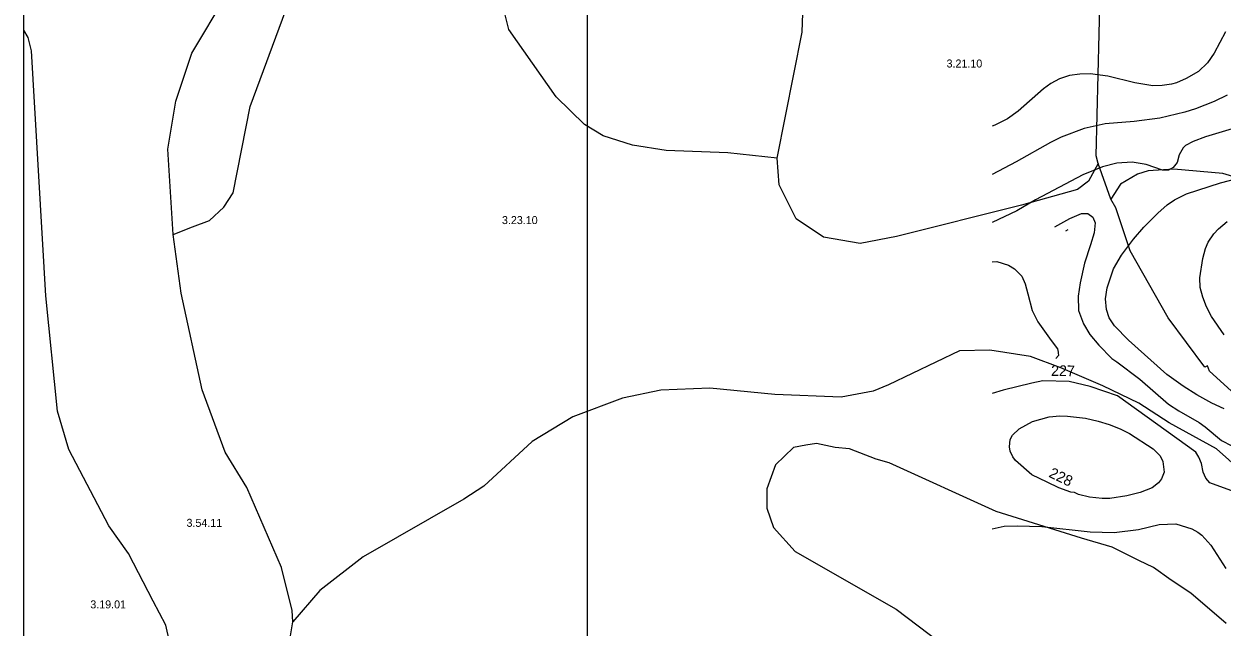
# Model space of a CAD drawing. Extents: x -662500 to -653478, y -1056827 to -1049993.
# Drawn here: x -662500 to -661377, y -1052752 to -1052187 of the extents above; entities that cross this region are included whole.
import ezdxf

# ---------------------------------------------------------------- set-up
doc = ezdxf.new("R2010")
doc.units = 0
for name, color, linetype in [('Vrstva 24', 7, 'Continuous'), ('Vrstva 7', 7, 'Continuous'), ('Vrstva 9', 7, 'Continuous')]:
    doc.layers.add(name, color=color, linetype=linetype)

msp = doc.modelspace()

# ---------------------------------------------------------------- linework, layer by layer
at = {"layer": 'Vrstva 24'}
for points in [[(-662500, -1052192.7), (-662500, -1052000), (-662500, -1051936.2)], [(-661794, -1052312.5), (-661840, -1052307.5), (-661898, -1052305.5), (-661929.5, -1052300.5), (-661957, -1052291.5), (-661974.5, -1052281), (-662001, -1052255), (-662045.5, -1052192), (-662051, -1052169.5), (-662044.5, -1052124.5), (-662027, -1052066), (-662005.5, -1052025.5), (-661977.2, -1052000), (-661965.5, -1051989.5), (-661936, -1051957)], [(-662360, -1052384), (-662342, -1052377), (-662326, -1052371), (-662312.5, -1052358.5), (-662304, -1052345), (-662288, -1052264), (-662254.5, -1052174), (-662230, -1052137.5), (-662217.5, -1052127.5), (-662164.5, -1052108), (-662148, -1052102), (-662118.5, -1052082), (-662096, -1052062.5), (-662083.5, -1052044.5), (-662081, -1052022), (-662089.6, -1052000), (-662090, -1051999), (-662093, -1051987), (-662096, -1051971)], [(-662360, -1052384), (-662365, -1052304), (-662357.5, -1052259), (-662342.5, -1052214), (-662310.5, -1052160), (-662296, -1052142), (-662284.5, -1052113), (-662279.5, -1052094.5), (-662275.5, -1052058.5), (-662267, -1052024)], [(-661794, -1052312.5), (-661770.5, -1052194.5), (-661769, -1052149.5), (-661771, -1052123), (-661774.5, -1052111), (-661778, -1052097), (-661789, -1052077.5), (-661800, -1052057), (-661815.5, -1052036)], [(-661493, -1052317.5), (-661495, -1052310.5), (-661491, -1052157.5), (-661494.5, -1052099), (-661494, -1052085), (-661500.5, -1052073), (-661505, -1052066), (-661512.5, -1052062), (-661538.5, -1052064.5), (-661566.5, -1052076), (-661606.5, -1052099.5), (-661625.5, -1052108), (-661655, -1052110), (-661691, -1052100), (-661737, -1052081), (-661750, -1052071.5)], [(-662500, -1053023.2), (-662500, -1052192.7)], [(-662500, -1053023.2), (-662494, -1053019.5), (-662486, -1053013), (-662479, -1053003.5), (-662475.3, -1053000), (-662456, -1052963.5), (-662427.5, -1052931), (-662414, -1052914), (-662397, -1052886.5), (-662363.5, -1052819.5), (-662359, -1052792.5), (-662358, -1052778), (-662363.5, -1052765.5), (-662367, -1052750), (-662379, -1052727.5), (-662402, -1052683), (-662420.5, -1052657), (-662458, -1052585.5), (-662468.5, -1052549.5), (-662479.5, -1052441.5), (-662493, -1052212), (-662496, -1052199.5), (-662500, -1052192.7)], [(-661493, -1052317.5), (-661502, -1052334), (-661512.5, -1052342), (-661565, -1052356.5), (-661682, -1052386), (-661716, -1052392.5), (-661750.5, -1052386.5), (-661776, -1052369.5), (-661792, -1052337.5), (-661794, -1052312.5)], [(-661481, -1052351), (-661493, -1052317.5)], [(-661227, -1052423), (-661235.5, -1052409), (-661260, -1052382), (-661282, -1052364), (-661292, -1052360), (-661300, -1052354), (-661317, -1052346), (-661346, -1052336), (-661376, -1052327), (-661422, -1052323), (-661446, -1052324.5), (-661456, -1052327.5), (-661472, -1052337), (-661481, -1052351)], [(-661304, -1052572.5), (-661358, -1052540), (-661388.5, -1052512), (-661390.5, -1052507), (-661393, -1052508.5), (-661427.5, -1052462), (-661463, -1052399.5), (-661476.5, -1052359), (-661481, -1052351)], [(-662248, -1052747), (-662248.5, -1052736.5), (-662258.5, -1052696), (-662291, -1052621), (-662311.5, -1052588), (-662333, -1052529.5), (-662352.5, -1052439), (-662360, -1052384)], [(-661359, -1052605.5), (-661382, -1052585), (-661426.5, -1052560.5), (-661455, -1052542), (-661488.5, -1052526), (-661528, -1052509), (-661556.5, -1052498.5), (-661594.5, -1052492.5), (-661623, -1052493), (-661689.5, -1052525), (-661704, -1052531), (-661734, -1052536.5), (-661796, -1052534), (-661857, -1052528), (-661903, -1052530), (-661939, -1052537.5), (-661985.5, -1052555), (-662023.5, -1052578), (-662069, -1052620), (-662087.5, -1052632), (-662182, -1052686), (-662222.5, -1052717.5), (-662248, -1052747)], [(-661373, -1052748.5), (-661406, -1052720), (-661424.5, -1052708), (-661441, -1052696), (-661455, -1052689.5), (-661480, -1052677), (-661508.5, -1052668.5), (-661588.5, -1052643.5), (-661689, -1052598), (-661701, -1052594.5), (-661726, -1052585), (-661739.5, -1052583.5), (-661757, -1052580), (-661767, -1052581.5), (-661778.5, -1052583.5), (-661795.5, -1052600), (-661803.5, -1052622.5), (-661803.5, -1052640.5), (-661797.5, -1052658.5), (-661777, -1052681), (-661682.5, -1052735), (-661569, -1052821)], [(-662346, -1053118), (-662332, -1053050.5), (-662319.3, -1053000), (-662298, -1052925), (-662255, -1052790), (-662248, -1052747)]]:
    msp.add_lwpolyline(points, dxfattribs=at)
at = {"layer": 'Vrstva 7'}
for p, q in [((-661373.6, -1052194.2), (-661384.2, -1052214.1)), ((-661390.5, -1052223.2), (-661399, -1052231.2)), ((-661384.2, -1052214.1), (-661390.5, -1052223.2)), ((-661510.2, -1052233.8), (-661519.9, -1052235.1)), ((-661500.6, -1052233.5), (-661510.2, -1052233.8)), ((-661483.9, -1052235.8), (-661500.6, -1052233.5)), ((-661399, -1052231.2), (-661410.4, -1052238)), ((-661537.4, -1052242.7), (-661544.2, -1052247.7)), ((-661529.1, -1052238.2), (-661537.4, -1052242.7)), ((-661519.9, -1052235.1), (-661529.1, -1052238.2)), ((-661458.6, -1052242), (-661483.9, -1052235.8)), ((-661441.6, -1052244.7), (-661458.6, -1052242)), ((-661433.1, -1052244.6), (-661441.6, -1052244.7)), ((-661424.1, -1052243.3), (-661433.1, -1052244.6)), ((-661419.5, -1052242), (-661424.1, -1052243.3)), ((-661410.4, -1052238), (-661419.5, -1052242)), ((-661544.2, -1052247.7), (-661567.9, -1052268.6)), ((-661372, -1052253.6), (-661384.1, -1052259.3)), ((-661401.7, -1052266.2), (-661411.6, -1052269.4)), ((-661384.1, -1052259.3), (-661401.7, -1052266.2)), ((-661578, -1052275.6), (-661589.9, -1052281.7)), ((-661567.9, -1052268.6), (-661578, -1052275.6)), ((-661459.2, -1052278.1), (-661486.4, -1052280.4)), ((-661435.1, -1052275), (-661459.2, -1052278.1)), ((-661411.6, -1052269.4), (-661435.1, -1052275)), ((-661589.9, -1052281.7), (-661592.2, -1052282.5)), ((-661506.2, -1052284.7), (-661527.6, -1052292.9)), ((-661486.4, -1052280.4), (-661506.2, -1052284.7)), ((-661367.4, -1052285.2), (-661392.3, -1052292.6)), ((-661537.7, -1052297.8), (-661569.7, -1052316)), ((-661527.6, -1052292.9), (-661537.7, -1052297.8)), ((-661411, -1052300.7), (-661413.4, -1052302.9)), ((-661403.8, -1052296.8), (-661411, -1052300.7)), ((-661392.3, -1052292.6), (-661403.8, -1052296.8)), ((-661417, -1052309.3), (-661418.8, -1052316.5)), ((-661413.4, -1052302.9), (-661417, -1052309.3)), ((-661569.7, -1052316), (-661592.2, -1052327.7)), ((-661488.8, -1052320.7), (-661507.4, -1052328.2)), ((-661475.4, -1052317.3), (-661488.8, -1052320.7)), ((-661461.2, -1052316.4), (-661475.4, -1052317.3)), ((-661448.1, -1052318.4), (-661461.2, -1052316.4)), ((-661432.8, -1052323.8), (-661448.1, -1052318.4)), ((-661426.9, -1052323.8), (-661432.8, -1052323.8)), ((-661422.6, -1052321.4), (-661426.9, -1052323.8)), ((-661418.8, -1052316.5), (-661422.6, -1052321.4)), ((-661507.4, -1052328.2), (-661551.6, -1052351.6)), ((-661410.2, -1052345.9), (-661378.4, -1052335.7)), ((-661378.4, -1052335.7), (-661335.3, -1052324.6)), ((-661421.5, -1052351.7), (-661410.2, -1052345.9)), ((-661551.6, -1052351.6), (-661569.3, -1052361.9)), ((-661437.1, -1052364), (-661428.3, -1052356.4)), ((-661428.3, -1052356.4), (-661421.5, -1052351.7)), ((-661569.3, -1052361.9), (-661592.2, -1052372.9)), ((-661533.5, -1052377), (-661519.7, -1052369)), ((-661519.7, -1052369), (-661508.5, -1052364.3)), ((-661508.5, -1052364.3), (-661502.7, -1052364.3)), ((-661502.7, -1052364.3), (-661498, -1052367.9)), ((-661498, -1052367.9), (-661495.8, -1052373)), ((-661450.1, -1052377.2), (-661437.1, -1052364)), ((-661523.4, -1052380.7), (-661521, -1052379.4)), ((-661495.8, -1052373), (-661496.6, -1052382.4)), ((-661459.8, -1052388.3), (-661450.1, -1052377.2)), ((-661384.4, -1052383.3), (-661380.3, -1052378.8)), ((-661380.3, -1052378.8), (-661372, -1052372)), ((-661496.6, -1052382.4), (-661500.3, -1052393.7)), ((-661471, -1052403.4), (-661459.8, -1052388.3)), ((-661392.5, -1052397.2), (-661389.8, -1052391.4)), ((-661389.8, -1052391.4), (-661384.4, -1052383.3)), ((-661500.3, -1052393.7), (-661505.8, -1052410.9)), ((-661395, -1052406.4), (-661392.5, -1052397.2)), ((-661592.2, -1052409.8), (-661587.9, -1052409.3)), ((-661587.9, -1052409.3), (-661577, -1052412.8)), ((-661577, -1052412.8), (-661571.5, -1052416.1)), ((-661505.8, -1052410.9), (-661509.9, -1052429.5)), ((-661478.5, -1052416.2), (-661471, -1052403.4)), ((-661397.7, -1052424.7), (-661395, -1052406.4)), ((-661571.5, -1052416.1), (-661564.7, -1052423)), ((-661564.7, -1052423), (-661561.4, -1052430.2)), ((-661484.6, -1052434), (-661478.5, -1052416.2)), ((-661397.4, -1052433.7), (-661397.7, -1052424.7)), ((-661561.4, -1052430.2), (-661558.9, -1052439.7)), ((-661509.9, -1052429.5), (-661511.6, -1052441.9)), ((-661486.1, -1052444.2), (-661484.6, -1052434)), ((-661394.9, -1052442.8), (-661397.4, -1052433.7)), ((-661558.9, -1052439.7), (-661554.9, -1052455.2)), ((-661511.6, -1052441.9), (-661511.4, -1052455.4)), ((-661485.3, -1052454.4), (-661486.1, -1052444.2)), ((-661391.3, -1052451.9), (-661394.9, -1052442.8)), ((-661554.9, -1052455.2), (-661549.4, -1052465.8)), ((-661511.4, -1052455.4), (-661506.8, -1052467.8)), ((-661482.6, -1052462.1), (-661485.3, -1052454.4)), ((-661386.6, -1052460.8), (-661391.3, -1052451.9)), ((-661549.4, -1052465.8), (-661537, -1052483.5)), ((-661506.8, -1052467.8), (-661500.7, -1052477.7)), ((-661477.6, -1052469.7), (-661482.6, -1052462.1)), ((-661464.6, -1052483.1), (-661477.6, -1052469.7)), ((-661375, -1052478.1), (-661386.6, -1052460.8)), ((-661500.7, -1052477.7), (-661492.5, -1052487.7)), ((-661537, -1052483.5), (-661531.2, -1052491.2)), ((-661531.2, -1052491.2), (-661530.6, -1052494.3)), ((-661492.5, -1052487.7), (-661480.3, -1052500.1)), ((-661428.6, -1052515.1), (-661464.6, -1052483.1)), ((-661530.1, -1052497.3), (-661532.7, -1052500.4)), ((-661530.6, -1052494.3), (-661530.6, -1052495)), ((-661530.6, -1052495), (-661530.1, -1052497.3)), ((-661480.3, -1052500.1), (-661475.6, -1052503.3)), ((-661475.6, -1052503.3), (-661453.8, -1052519.6)), ((-661413.3, -1052526.1), (-661428.6, -1052515.1)), ((-661555.3, -1052523.3), (-661581.9, -1052530)), ((-661544.8, -1052521.3), (-661555.3, -1052523.3)), ((-661520.1, -1052521.8), (-661544.8, -1052521.3)), ((-661500.6, -1052526.4), (-661520.1, -1052521.8)), ((-661474.9, -1052535.2), (-661500.6, -1052526.4)), ((-661453.8, -1052519.6), (-661426.9, -1052542.9)), ((-661400.5, -1052534.2), (-661413.3, -1052526.1)), ((-661581.9, -1052530), (-661592.2, -1052533.2)), ((-661401.5, -1052587.9), (-661474.9, -1052535.2)), ((-661386.4, -1052542.2), (-661400.5, -1052534.2)), ((-661426.9, -1052542.9), (-661417.5, -1052549.2)), ((-661375, -1052547.3), (-661386.4, -1052542.2)), ((-661567.2, -1052566.3), (-661554.4, -1052559.2)), ((-661554.4, -1052559.2), (-661538.8, -1052554.9)), ((-661538.8, -1052554.9), (-661528.9, -1052554.1)), ((-661528.9, -1052554.1), (-661521.8, -1052554.2)), ((-661521.8, -1052554.2), (-661504.8, -1052556.2)), ((-661504.8, -1052556.2), (-661492.9, -1052558.9)), ((-661492.9, -1052558.9), (-661482.7, -1052562)), ((-661417.5, -1052549.2), (-661398.4, -1052560.3)), ((-661398.4, -1052560.3), (-661392.6, -1052564.4)), ((-661573.3, -1052572.1), (-661567.2, -1052566.3)), ((-661482.7, -1052562), (-661472.5, -1052566)), ((-661472.5, -1052566), (-661463.5, -1052570.4)), ((-661463.5, -1052570.4), (-661441.5, -1052584.8)), ((-661392.6, -1052564.4), (-661377.4, -1052577.2)), ((-661576.1, -1052583.1), (-661575.5, -1052576)), ((-661575.5, -1052576), (-661573.3, -1052572.1)), ((-661377.4, -1052577.2), (-661367.7, -1052582.1)), ((-661575.5, -1052587.1), (-661576.1, -1052583.1)), ((-661572.9, -1052592.5), (-661575.5, -1052587.1)), ((-661570.4, -1052595.7), (-661572.9, -1052592.5)), ((-661441.5, -1052584.8), (-661437.7, -1052588.6)), ((-661437.7, -1052588.6), (-661434.8, -1052591.6)), ((-661434.8, -1052591.6), (-661432.3, -1052596.7)), ((-661398.5, -1052592.8), (-661401.5, -1052587.9)), ((-661396.1, -1052598.7), (-661398.5, -1052592.8)), ((-661555.3, -1052609.1), (-661570.4, -1052595.7)), ((-661432.3, -1052596.7), (-661431, -1052606.6)), ((-661394.6, -1052606.6), (-661396.1, -1052598.7)), ((-661540.8, -1052616.1), (-661555.3, -1052609.1)), ((-661529.8, -1052621.4), (-661540.8, -1052616.1)), ((-661433.5, -1052612.9), (-661436.5, -1052616.7)), ((-661431, -1052606.6), (-661433.5, -1052612.9)), ((-661391.9, -1052612.3), (-661394.6, -1052606.6)), ((-661388.2, -1052616.7), (-661391.9, -1052612.3)), ((-661518.6, -1052625.5), (-661529.8, -1052621.4)), ((-661515.3, -1052625.9), (-661518.6, -1052625.5)), ((-661511.4, -1052627.6), (-661515.3, -1052625.9)), ((-661501.1, -1052630.2), (-661511.4, -1052627.6)), ((-661453.5, -1052625.8), (-661466, -1052629)), ((-661442.5, -1052621.5), (-661453.5, -1052625.8)), ((-661436.5, -1052616.7), (-661442.5, -1052621.5)), ((-661365.2, -1052625.3), (-661388.2, -1052616.7)), ((-661489.2, -1052631.4), (-661501.1, -1052630.2)), ((-661481.9, -1052631.3), (-661489.2, -1052631.4)), ((-661466, -1052629), (-661481.9, -1052631.3)), ((-661592.2, -1052659.9), (-661581.2, -1052657.4)), ((-661581.2, -1052657.4), (-661568.9, -1052657)), ((-661568.9, -1052657), (-661545.9, -1052657.8)), ((-661545.9, -1052657.8), (-661500.6, -1052662.6)), ((-661477.9, -1052663.2), (-661455.2, -1052660.6)), ((-661455.2, -1052660.6), (-661435.7, -1052655.8)), ((-661435.7, -1052655.8), (-661420.1, -1052655.2)), ((-661420.1, -1052655.2), (-661405.1, -1052659.8)), ((-661405.1, -1052659.8), (-661399.4, -1052663)), ((-661500.6, -1052662.6), (-661477.9, -1052663.2)), ((-661399.4, -1052663), (-661395.9, -1052665.9)), ((-661395.9, -1052665.9), (-661387.5, -1052675.2)), ((-661387.5, -1052675.2), (-661373.3, -1052697.1))]:
    msp.add_line(p, q, dxfattribs=at)
at = {"layer": 'Vrstva 9'}
msp.add_line((-661971.6, -1054269.4), (-661971.6, -1050953), dxfattribs=at)

# ---------------------------------------------------------------- texts
at = {"layer": 'Vrstva 24'}
for s, p in [('3.21.10', (-661635.1, -1052227.6)), ('3.23.10', (-662051.9, -1052374.3)), ('3.54.11', (-662347.6, -1052658)), ('3.19.01', (-662437.8, -1052734.4))]:
    msp.add_text(s, height=7.5, dxfattribs=at).set_placement(p)
at = {"layer": 'Vrstva 7'}
for s, rotation, p in [('227', 359.0126, (-661537.2, -1052516.5)), ('228', 334.36, (-661540, -1052610.9))]:
    msp.add_text(s, height=10, rotation=rotation, dxfattribs=at).set_placement(p)

doc.saveas('drawing.dxf')
